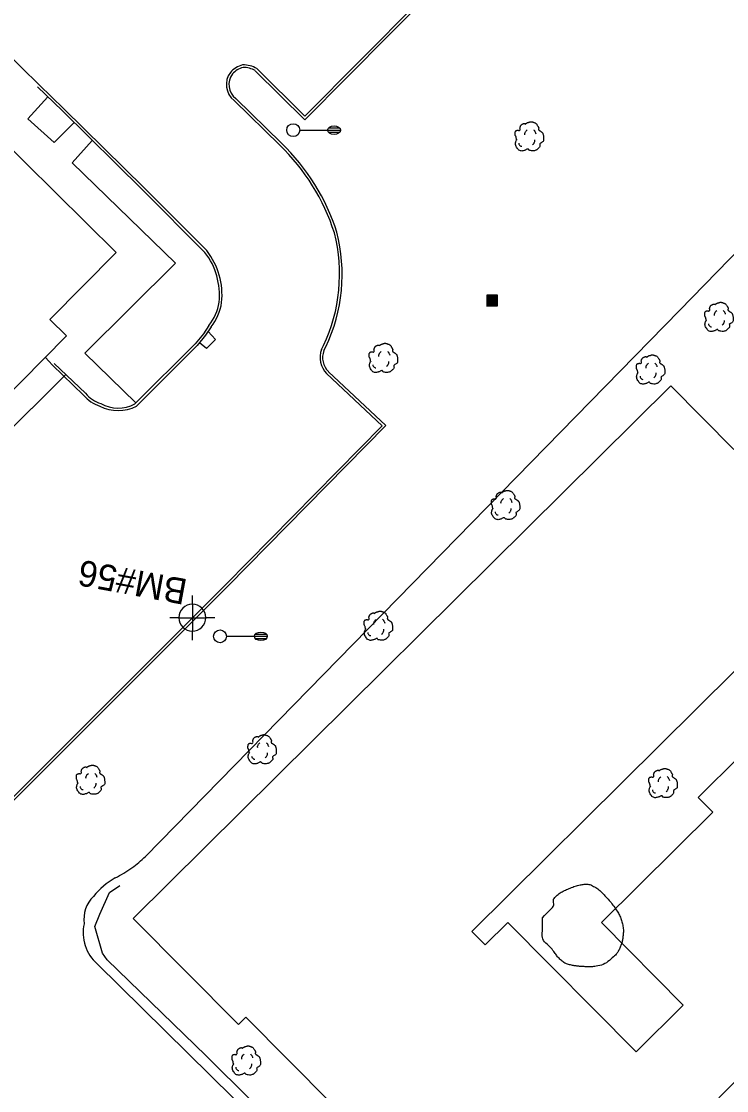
# Model space of a CAD drawing. Extents: x 2145380 to 2156929, y 139568 to 149130.
# Drawn here: x 2151370.2 to 2151534.2, y 143345.6 to 143594.3 of the extents above; entities that cross this region are included whole.
import ezdxf

# ---------------------------------------------------------------- set-up
doc = ezdxf.new("R2010")
doc.units = 0
for name, color, linetype in [('SURV_Benchmark', 7, 'Continuous'), ('SURV_Text', 7, 'Continuous'), ('TOPO_Asphalt', 7, 'Continuous'), ('TOPO_Building', 7, 'Continuous'), ('TOPO_Curb Back', 7, 'Continuous'), ('TOPO_DRAIN_Inlet Grate', 7, 'Continuous'), ('TOPO_Fence', 7, 'Continuous'), ('TOPO_Light Pole', 7, 'Continuous'), ('TOPO_Misc', 7, 'Continuous'), ('TOPO_Sidewalk', 7, 'Continuous'), ('TOPO_Tree', 7, 'Continuous'), ('TOPO_Tree Line', 7, 'Continuous'), ('TOPO_Wall Freestanding', 7, 'Continuous')]:
    doc.layers.add(name, color=color, linetype=linetype)

# ---------------------------------------------------------------- blocks, each defined once
blk = doc.blocks.new('LP')
at = {"layer": 'TOPO_Light Pole'}
blk.add_line((3.81, 0), (20.32, 0), dxfattribs=at)
for points in [[(20.32, 0), (27.94, 0)], [(20.32, 0), (23.5, 0)], [(20.83, 1.27), (27.43, 1.27)], [(20.83, 1.27), (23.5, 1.27)], [(23.71, 1.27), (27.43, 1.27)], [(23.71, 0), (27.94, 0)], [(20.83, -1.27), (27.43, -1.27)], [(20.83, -1.27), (23.5, -1.27)], [(23.71, -1.27), (27.43, -1.27)]]:
    blk.add_lwpolyline(points, dxfattribs=at)
blk.add_circle((0, 0), 3.81, dxfattribs=at)
blk.add_ellipse((24.13, 0), major_axis=(3.81, 0), ratio=0.666667, dxfattribs=at)
blk = doc.blocks.new('CB')
at = {"layer": 'TOPO_Misc'}
for p, q in [((-3.08, 2.99), (3.24, 2.99)), ((-3.08, 2.68), (3.24, 2.68)), ((-3.08, 2.36), (3.24, 2.36)), ((-3.08, 2.05), (3.24, 2.05)), ((-3.08, 1.73), (3.24, 1.73)), ((-3.08, 1.4), (3.24, 1.4)), ((-3.08, 1.1), (3.24, 1.1)), ((-3.08, 0.77), (3.24, 0.77)), ((-3.08, 0.46), (3.24, 0.46)), ((-3.08, 0.14), (3.24, 0.14)), ((-3.08, -0.17), (3.24, -0.17)), ((-3.08, -0.48), (3.24, -0.48)), ((-3.08, -0.8), (3.24, -0.8)), ((-3.08, -1.11), (3.26, -1.11)), ((-3.08, -1.43), (3.26, -1.43)), ((-3.08, -1.75), (3.26, -1.75)), ((-3.08, -2.07), (3.26, -2.07)), ((-3.08, -2.39), (3.26, -2.39)), ((-3.08, -2.7), (3.26, -2.7)), ((-3.08, -3.02), (3.26, -3.02))]:
    blk.add_line(p, q, dxfattribs=at)
blk.add_lwpolyline([(3.26, -3.29), (3.24, 3.05), (-3.09, 3.04), (-3.08, -3.3), (3.26, -3.29)], dxfattribs=at)
blk = doc.blocks.new('TREE')
at = {"layer": 'TOPO_Tree'}
for points in [[(-14.1, -0.4), (-14.2, 0.5), (-14.4, 1.4), (-14.6, 2.3), (-14.8, 3.2), (-15.5, 4), (-15.7, 4.9), (-15.8, 5.6), (-15.7, 6.3), (-15.7, 7), (-15.6, 7.9), (-15.7, 8.8), (-15.1, 9.7), (-14.6, 10.4), (-13.8, 10.5), (-13, 10.7), (-12.2, 11), (-11.1, 10), (-10.4, 10.7), (-9.4, 11.7), (-10.3, 13.3), (-9.8, 14.4), (-9.6, 15.1), (-9.3, 15.9), (-8.8, 16.5), (-8.2, 17.3), (-7.5, 17.7), (-6.7, 18.1), (-6.1, 18.4), (-5.6, 18.6), (-5.1, 18.7), (-4.5, 18.7), (-4, 18.5), (-3.5, 18.1)], [(-3.5, 17.6), (-3.1, 18.3), (-2.6, 18.8), (-1.9, 19.2), (-1, 19.7), (-0.2, 20), (0.7, 20.2), (1.6, 20.5), (2.5, 20.8), (3.4, 20.8), (4.1, 20.7), (4.8, 20.5), (5.5, 20.2), (6.4, 19.9), (7.3, 19.7), (8.2, 19.2), (9.4, 18.4), (10, 17.2), (10.8, 16), (11.2, 15.3), (11.6, 14.6), (11.9, 13.9), (12.2, 13.1), (11.4, 12), (11.9, 11.2), (12, 11), (12.2, 10.9), (12.4, 10.7), (12.9, 10.4), (13.5, 10), (14, 9.7), (14.7, 9.2), (15.4, 8.7), (16.1, 8.1), (16.7, 7.5), (16.9, 6.7), (17.1, 6), (17.6, 4.4), (17.7, 2.8), (17.7, 1.2), (17.7, -0.2), (17.8, -2.2), (16.6, -3), (15.5, -3.8), (14.3, -4.6), (13.2, -5.3)], [(13.2, -5.3), (13.3, -5.8), (13.4, -6.3), (13.4, -6.7), (13.8, -8.5), (12.2, -10), (10.8, -11.5), (10, -12.3), (9.1, -12.8), (8.2, -13.1), (6, -13.8), (3.3, -13.6), (1.3, -13.1), (0.5, -12.9), (-0.1, -11.4), (-0.8, -11.5), (-2, -11.6), (-3.3, -12.8), (-4.5, -13.1), (-6.1, -13.5), (-7.8, -14), (-9.3, -13.6), (-11.4, -13.1), (-12.8, -11.4), (-14.1, -9.4), (-15.3, -7.3), (-15.6, -5.1), (-15.1, -3), (-14.9, -1.9), (-13.9, -0.8), (-13.5, 0.1)], [(-4.2, 5.1), (-4.5, 6.1), (-4.3, 7.2), (-3.8, 8.2), (-3.3, 9.3), (-2.7, 10.3), (-1.6, 11)], [(5.9, 11.2), (6.5, 10.7), (7, 10.2), (7.4, 9.5), (7.9, 8.6), (8.3, 7.6), (8.5, 6.6)], [(-11.4, -4.5), (-11.5, -5.4), (-11, -6.3), (-10.1, -7.2), (-9.3, -8), (-8.5, -8.3), (-7.7, -8.1)], [(4.8, -6.3), (5.7, -5.7), (6.3, -4.9), (6.8, -3.9), (7.4, -2.8), (7.6, -1.7), (7.5, -0.6)]]:
    blk.add_open_spline(points, degree=3, dxfattribs=at)
blk = doc.blocks.new('BM')
at = {"layer": 'SURV_Benchmark'}
for p, q in [((0, 2.49), (0, 4.15)), ((-2.49, 0), (-4.16, 0)), ((4.16, 0), (2.49, 0)), ((0, -4.16), (0, -2.49))]:
    blk.add_line(p, q, dxfattribs=at)
for points in [[(0, 2.49), (0, 2.49), (0, 0), (2.49, 0), (2.49, 0), (2.49, 0)], [(0, 2.49), (0, 2.49), (0, 0), (2.49, 0), (2.49, 0), (2.49, 0), (2.49, 0)], [(-2.5, 0), (-2.49, 0), (0, 0), (0, -2.49), (0, -2.49)], [(-2.5, 0), (-2.49, 0), (0, 0), (0, -2.49), (0, -2.49)]]:
    blk.add_lwpolyline(points, dxfattribs=at)
for start, end in [(90.0638, 180.0068), (0.0638, 90.0068), (0.0638, 90.0068), (180.0638, 270.0068), (180.0638, 270.0068), (269.9472, 359.9927)]:
    blk.add_arc((0, 0), 2.5, start, end, dxfattribs=at)

msp = doc.modelspace()

# ---------------------------------------------------------------- linework, layer by layer
at = {"layer": 'TOPO_Asphalt'}
for p, q in [((2151370.26, 143583.53), (2151374.36, 143579.48)), ((2151380.5, 143512.18), (2151340.77, 143472.49))]:
    msp.add_line(p, q, dxfattribs=at)
msp.add_lwpolyline([(2151377.43, 143514.29), (2151376.56, 143515.24), (2151375.78, 143516.12)], dxfattribs=at)
at = {"layer": 'TOPO_Building'}
msp.add_lwpolyline([(2151254.02, 143479.01), (2151337.75, 143563.85), (2151341.66, 143559.99), (2151356.88, 143575.42), (2151392.22, 143540.54), (2151376.84, 143524.96), (2151380.72, 143521.13), (2151297.15, 143436.44)], close=True, dxfattribs=at)
for points in [[(2151589.49, 143203.75), (2151491.3, 143302.84), (2151485.56, 143297.16), (2151471.14, 143311.71), (2151472.05, 143312.61), (2151422.41, 143362.7), (2151420.66, 143360.96), (2151396.2, 143385.64), (2151521.19, 143509.5), (2151535.84, 143494.72)], [(2151562.21, 143469.15), (2151474.9, 143382.62), (2151478, 143379.49), (2151483.27, 143384.71), (2151513.1, 143354.6), (2151524.09, 143365.48), (2151505.05, 143384.69), (2151530.95, 143410.35), (2151527.52, 143413.81), (2151556.6, 143442.63)], [(2151550.18, 143361.6), (2151532.36, 143343.94), (2151630.79, 143244.61)]]:
    msp.add_lwpolyline(points, dxfattribs=at)
at = {"layer": 'TOPO_Curb Back'}
for points in [[(2151424.57, 143582.8), (2151436.08, 143571.34), (2151475.48, 143611.12), (2151478.14, 143609.67)], [(2151424.94, 143583.28), (2151436.08, 143572.19), (2151475.37, 143611.86), (2151478.43, 143610.2)], [(2151363.6, 143588.76), (2151367.68, 143586.08), (2151370.56, 143583.24)], [(2151373.94, 143579.05), (2151379.66, 143573.52), (2151398.35, 143555.11), (2151412.88, 143540.55)], [(2151374.36, 143579.48), (2151380.08, 143573.95), (2151398.77, 143555.53), (2151413.33, 143540.95)], [(2151430.27, 143565.49), (2151419.64, 143575.86)], [(2151430.69, 143565.92), (2151420.04, 143576.31)], [(2151413.8, 143523.56), (2151412.54, 143521.61), (2151410.59, 143519.28), (2151396.57, 143505.29)], [(2151414.29, 143523.21), (2151413.02, 143521.26), (2151411.04, 143518.88), (2151396.93, 143504.8)], [(2151439.96, 143517.96), (2151440.47, 143518.86)], [(2151440.51, 143517.7), (2151441, 143518.59)], [(2151316.48, 143371.69), (2151322.22, 143366.62), (2151371.2, 143415.91), (2151418.19, 143462.91), (2151454.94, 143500.25), (2151441.58, 143512.8)], [(2151384.66, 143507.37), (2151377.43, 143514.29)], [(2151385.1, 143507.78), (2151377.85, 143514.73)], [(2151316.91, 143372.1), (2151322.2, 143367.45), (2151370.78, 143416.33), (2151417.77, 143463.34), (2151454.08, 143500.23), (2151441.17, 143512.37)]]:
    msp.add_lwpolyline(points, dxfattribs=at)
for centre, radius, start, end in [((2151422.62, 143579.58), 4.77, 143.6142, 231.2802), ((2151423, 143578.65), 5.65, 103.9826, 138.3038), ((2151423.01, 143578.65), 5.05, 104.7051, 137.9839), ((2151421.84, 143578.1), 6.04, 59.1031, 91.8568), ((2151421.84, 143578.1), 5.44, 59.8577, 91.182), ((2151422.62, 143579.58), 4.17, 143.9951, 231.6686), ((2151395.85, 143529.94), 49.49, 17.7802, 45.9245), ((2151395.85, 143529.94), 50.09, 17.7588, 45.9231), ((2151405.02, 143535.47), 39.15, 334.9019, 14.1707), ((2151405.02, 143535.47), 39.75, 334.8708, 14.1978), ((2151399.86, 143530.59), 16.39, 354.2317, 37.4344), ((2151399.86, 143530.59), 16.99, 354.1737, 37.5679), ((2151404.7, 143530.78), 11.61, 321.5818, 350.9284), ((2151404.7, 143530.78), 12.21, 321.7194, 351.0092), ((2151444.9, 143516.1), 5.28, 159.3896, 224.9597), ((2151444.9, 143516.1), 4.67, 159.9284, 224.847), ((2151390.6, 143512.09), 6.98, 218.1114, 254.043), ((2151390.6, 143512.08), 7.58, 218.4386, 253.5504), ((2151392.71, 143512.83), 8.48, 241.6089, 297.1425), ((2151392.71, 143512.83), 9.08, 242.0203, 297.7461)]:
    msp.add_arc(centre, radius, start, end, dxfattribs=at)
at = {"layer": 'TOPO_DRAIN_Inlet Grate'}
msp.add_lwpolyline([(2151413.6, 143522.15), (2151415.3, 143520.25), (2151413.26, 143518.21), (2151411.58, 143519.52)], dxfattribs=at)
at = {"layer": 'TOPO_Fence'}
msp.add_lwpolyline([(2151617.6, 143131.61), (2151614.87, 143153), (2151578.88, 143189.14), (2151498.33, 143269.16), (2151413.09, 143353.79), (2151390.16, 143376.02), (2151389.07, 143377.54), (2151387.27, 143383.79), (2151388.4, 143386.65), (2151390.7, 143391.66), (2151393.12, 143393.33)], dxfattribs=at)
at = {"layer": 'TOPO_Sidewalk'}
for points in [[(2151382.44, 143570.78), (2151377.83, 143566.07), (2151371.7, 143571.57), (2151376.32, 143576.75)], [(2151396.82, 143505.53), (2151384.98, 143517.08), (2151406.01, 143538.05), (2151382.01, 143561.38), (2151386.69, 143566.59)]]:
    msp.add_lwpolyline(points, dxfattribs=at)
at = {"layer": 'TOPO_Tree Line'}
msp.add_open_spline([(2151491.38, 143385.8), (2151491.36, 143384.54), (2151491.33, 143383.28), (2151491.31, 143382.02), (2151491.28, 143380.47), (2151492.89, 143379.39), (2151493.85, 143378.12), (2151494.45, 143377.32), (2151494.98, 143376.54), (2151495.77, 143375.86), (2151496.51, 143375.23), (2151497.4, 143374.92), (2151498.33, 143374.74), (2151499.16, 143374.58), (2151499.99, 143374.5), (2151500.82, 143374.45), (2151501.67, 143374.39), (2151502.53, 143374.37), (2151503.38, 143374.48), (2151505.09, 143374.69), (2151506.59, 143375.54), (2151507.97, 143376.82), (2151508.66, 143377.46), (2151509.06, 143378.15), (2151509.41, 143378.98), (2151509.75, 143379.78), (2151509.97, 143380.58), (2151510.06, 143381.4), (2151510.18, 143382.46), (2151510.15, 143383.58), (2151509.86, 143384.64), (2151509.57, 143385.68), (2151509.15, 143386.64), (2151508.55, 143387.56), (2151507.74, 143388.8), (2151506.85, 143389.85), (2151505.85, 143390.93), (2151505.04, 143391.79), (2151504.27, 143392.53), (2151503.18, 143393.14), (2151502.37, 143393.58), (2151501.48, 143393.68), (2151500.66, 143393.55), (2151499.51, 143393.37), (2151498.37, 143392.98), (2151497.24, 143392.47), (2151496.16, 143391.99), (2151495.18, 143391.49), (2151494.35, 143390.64), (2151493.69, 143389.97), (2151494.17, 143388.71), (2151493.55, 143388.06), (2151492.82, 143387.31), (2151492.1, 143386.55), (2151491.38, 143385.8)], degree=3, dxfattribs=at)
at = {"layer": 'TOPO_Wall Freestanding'}
for points in [[(2151399.05, 143400.08), (2151523.18, 143527.01), (2151581.28, 143586.63)], [(2151606.98, 143158), (2151574.31, 143190.77), (2151498.41, 143266.1), (2151387.85, 143375.09)]]:
    msp.add_lwpolyline(points, dxfattribs=at)
for centre, radius, start, end in [((2151381.28, 143417.93), 25.19, 305.4332, 314.8723), ((2151373.71, 143429.88), 39.33, 297.7427, 304.3154), ((2151401.45, 143378.89), 18.74, 120.2474, 140.6073), ((2151392.1, 143385.49), 7.37, 134.0813, 188.4108), ((2151394.08, 143382.28), 9.52, 167.0526, 229.1087)]:
    msp.add_arc(centre, radius, start, end, dxfattribs=at)

# ---------------------------------------------------------------- block references
at = {"layer": 'SURV_Benchmark', "xscale": 1.25, "yscale": 1.25}
msp.add_blockref('BM', (2151409.95, 143455.59), dxfattribs=at)
at = {"layer": 'TOPO_Light Pole', "xscale": 0.39370000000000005, "yscale": 0.3937000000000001}
for p in [(2151433.4, 143568.97), (2151416.38, 143451.26)]:
    msp.add_blockref('LP', p, dxfattribs=at)
at = {"layer": 'TOPO_Misc', "xscale": 0.39370000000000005, "yscale": 0.3937000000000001}
msp.add_blockref('CB', (2151479.64, 143529.37), dxfattribs=at)
at = {"layer": 'TOPO_Tree', "xscale": 0.19685000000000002, "yscale": 0.19685000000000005}
for p in [(2151488.1, 143566.84), (2151532.18, 143524.85), (2151454.16, 143515.31), (2151516.29, 143512.62), (2151482.57, 143481.11), (2151452.99, 143453.03), (2151425.97, 143424.3), (2151386.08, 143417.21), (2151519.18, 143416.44), (2151422.28, 143351.92)]:
    msp.add_blockref('TREE', p, dxfattribs=at)

# ---------------------------------------------------------------- texts
at = {"layer": 'SURV_Text'}
msp.add_text('BM#56', height=6, rotation=169.4936, dxfattribs=at).set_placement((2151409.08, 143464.46))

doc.saveas('drawing.dxf')
